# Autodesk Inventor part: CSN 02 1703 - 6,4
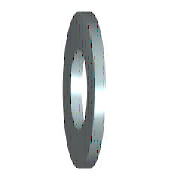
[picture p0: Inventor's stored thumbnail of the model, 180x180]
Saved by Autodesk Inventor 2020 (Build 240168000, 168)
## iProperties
Created: 2019-01
Part Number: CSN 02 1703 - 6,4
Material: Ocel, měkká
Description: Podložky pro šrouby s válcovou a půlkulovou hlavou
Document SubType Name: Modeling
Standard: CSN 02 1703
Designer: doma
Standards Organization: CSN
Language: cs-CZ
Size Designation: 6,4
Categories: <MemberInstance><Categories><Category DisplayName="Spojovací materiál" InternalName="e4da775c-781d-43d5-af7c-5136215cf5a6" Mnemonic="FSTN"><Category DisplayName
Density: 7.85 g/cm^3
Appearance: Pololeštěná
IsCustomPart: 0
Author: doma
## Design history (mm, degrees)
sketch "Náčrt"
  geometry: C1 r 5.5 at (0, 0); C2 r 3.2 at (0, 0); 1 further point
  constraints: 2 centre point, 2 coincident
  dimensions: "d0" = 6.4 diameter of C2 (= SD1); "d1" = 11 diameter of C1 (= SD2)
extrude "Těleso" new body sketch "Náčrt" distance "d2" = 1.2 (= SD); taper "d3" = 0 deg
workaxis "Work Axis1"
workplane "Work Plane1"
body "Solid1"
other parameters: "SD1" = 6.4 [user parameter; used in 1 equation term], "SD2" = 11 [user parameter; used in 1 equation term], "SD" = 1.2 [user parameter; used in 1 equation term], "d4" = 0, "d5" = 0, "d6" = 0, "d7" = 0, "NND" = 6 [user parameter]
